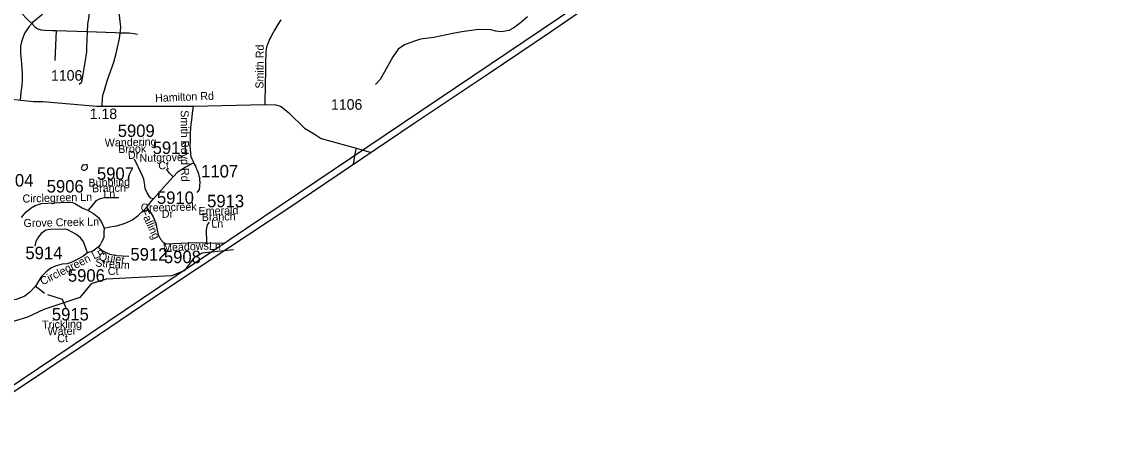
# Model space of a CAD drawing. Extents: x 1383679 to 1536984, y 460658 to 651027.
# Drawn here: x 1405913 to 1418729, y 488156 to 493101 of the extents above; entities that cross this region are included whole.
import ezdxf

# ---------------------------------------------------------------- set-up
doc = ezdxf.new("R2010")
doc.units = 0
for name, color, linetype in [('Default', 7, 'Continuous'), ('Exist Boundary Political City Limit New', 7, 'Continuous'), ('Exist Boundary Political StateLine', 7, 'Continuous'), ('Exist Hydrographic Creek Single Shore', 7, 'Continuous'), ('Exist Hydrographic Misc Water Feature', 7, 'Continuous'), ('Exist Road Non-System Secondary Historical Number Label', 7, 'Continuous'), ('Exist Road Non-System Type 51', 7, 'Continuous'), ('Exist Road Non-System Type 51 Label', 7, 'Continuous'), ('Exist Road Secondary Mileage Hundredths English Label', 7, 'Continuous'), ('Exist Road Secondary Type 51 Attributed', 7, 'Continuous'), ('Exist Road Secondary Type 51 Label', 7, 'Continuous'), ('Exist Road Secondary Type 51 Number Label', 7, 'Continuous'), ('Map Preparation Boundary City Limit Buffer Line', 7, 'Continuous')]:
    doc.layers.add(name, color=color, linetype=linetype)

msp = doc.modelspace()

# ---------------------------------------------------------------- linework, layer by layer
at = {"layer": 'Default'}
msp.add_lwpolyline([(1418935, 497828), (1418342, 497382), (1417593, 496830), (1416984, 496373), (1416229, 495820), (1415794, 495504), (1404876, 488156)], dxfattribs=at)
at = {"layer": 'Exist Boundary Political City Limit New'}
msp.add_lwpolyline([(1418935, 497828), (1418342, 497382), (1417593, 496830), (1416984, 496373), (1416229, 495820), (1415794, 495504), (1404876, 488156)], dxfattribs=at)
at = {"layer": 'Exist Boundary Political StateLine'}
msp.add_lwpolyline([(1418935, 497828), (1418342, 497382), (1417593, 496830), (1416984, 496373), (1416229, 495820), (1415409, 495224), (1414916, 494852), (1414652, 494666), (1413810, 494099), (1412999, 493532), (1412192, 492975), (1411452, 492477), (1410572, 491891), (1409804, 491375), (1409060, 490873), (1408385, 490425), (1407598, 489902), (1406702, 489298), (1405746, 488656)], dxfattribs=at)
at = {"layer": 'Exist Hydrographic Creek Single Shore'}
msp.add_lwpolyline([(1408427, 490392), (1408055, 490355), (1407962, 490301), (1407843, 490142), (1407692, 490086), (1406915, 490046), (1406739, 489991), (1406603, 489826), (1406175, 489684), (1405981, 489596), (1405604, 489479)], dxfattribs=at)
at = {"layer": 'Exist Hydrographic Misc Water Feature'}
for points in [[(1411916, 493157), (1411834, 493085), (1411757, 493026), (1411697, 492996), (1411608, 492979), (1411540, 492988), (1411483, 493002), (1411335, 493006), (1411136, 492978), (1411032, 492961), (1410805, 492911), (1410648, 492892), (1410564, 492865), (1410459, 492824), (1410384, 492775), (1410320, 492682), (1410222, 492506), (1410169, 492413), (1410115, 492356)], [(1406691, 491404), (1406655, 491399), (1406635, 491396), (1406631, 491385), (1406620, 491360), (1406626, 491346), (1406650, 491339), (1406664, 491338), (1406680, 491345), (1406690, 491358), (1406695, 491368), (1406691, 491404)]]:
    msp.add_lwpolyline(points, dxfattribs=at)
at = {"layer": 'Exist Road Non-System Type 51'}
for q in [(1406309, 492639), (1406692, 492982)]:
    msp.add_line((1406324, 492994), q, dxfattribs=at)
for points in [[(1405098, 493728), (1405117, 493706), (1405147, 493701), (1405289, 493687), (1405330, 493683), (1405359, 493675), (1405389, 493660), (1405418, 493641), (1405663, 493443), (1405870, 493251), (1405915, 493198), (1405975, 493135), (1406034, 493078)], [(1406457, 493650), (1406403, 493551), (1406330, 493410), (1406289, 493344), (1406246, 493280), (1406199, 493227), (1406146, 493174), (1406079, 493118), (1406044, 493090), (1406034, 493078)], [(1406988, 493622), (1406826, 493591), (1406800, 493581), (1406770, 493559), (1406748, 493536), (1406734, 493511), (1406724, 493482), (1406721, 493453), (1406721, 493419), (1406722, 493366), (1406722, 493330), (1406721, 493294), (1406705, 493133), (1406700, 493097), (1406697, 493067), (1406692, 492982)], [(1407083, 492966), (1407087, 492992), (1407089, 493040), (1407084, 493103), (1407074, 493178), (1407057, 493264), (1407006, 493527), (1406988, 493622)], [(1406034, 493078), (1405998, 493038), (1405961, 492980), (1405944, 492953), (1405922, 492896), (1405912, 492862), (1405901, 492809), (1405898, 492768), (1405898, 492765)], [(1406034, 493078), (1406070, 493038), (1406104, 493017), (1406146, 493003), (1406189, 492998), (1406274, 492995), (1406324, 492994)], [(1408988, 493122), (1408955, 493066), (1408915, 492998), (1408875, 492927), (1408869, 492915), (1408856, 492891), (1408846, 492869), (1408843, 492861), (1408838, 492850), (1408834, 492839), (1408830, 492828), (1408825, 492812), (1408821, 492794), (1408817, 492779), (1408815, 492763), (1408813, 492747), (1408812, 492731), (1408811, 492713), (1408811, 492697), (1408809, 492651), (1408806, 492505), (1408803, 492367), (1408800, 492119)], [(1406692, 492982), (1406685, 492795), (1406682, 492744), (1406677, 492692), (1406669, 492644), (1406627, 492401), (1406618, 492376), (1406598, 492355)], [(1406692, 492982), (1407023, 492971), (1407083, 492966)], [(1406868, 492098), (1406874, 492198), (1406881, 492239), (1406895, 492289), (1406934, 492408), (1407006, 492621), (1407036, 492722), (1407074, 492900), (1407083, 492966)], [(1407083, 492966), (1407148, 492968), (1407190, 492968), (1407248, 492961), (1407290, 492951)], [(1405898, 492765), (1405901, 492723), (1405908, 492649), (1405916, 492546), (1405921, 492478), (1405919, 492413), (1405914, 492342), (1405905, 492258), (1405896, 492173)], [(1407949, 492098), (1407939, 492016), (1407928, 491933), (1407922, 491886), (1407917, 491834), (1407914, 491786), (1407913, 491725), (1407912, 491681), (1407911, 491631), (1407912, 491584), (1407916, 491540), (1407919, 491519), (1407922, 491505), (1407926, 491493), (1407933, 491474), (1407948, 491441), (1407954, 491427)], [(1409853, 491408), (1409872, 491533), (1409880, 491568), (1409889, 491601)], [(1407479, 490997), (1407447, 491005), (1407427, 491028), (1407402, 491068), (1407381, 491122), (1407373, 491182), (1407365, 491233), (1407344, 491277), (1407251, 491469)], [(1407711, 491258), (1407771, 491324), (1407856, 491372), (1407954, 491427)], [(1407954, 491427), (1407976, 491384), (1407986, 491362), (1407995, 491339), (1408003, 491317), (1408011, 491295), (1408017, 491275), (1408018, 491271), (1408023, 491250), (1408025, 491238), (1408026, 491224), (1408028, 491195), (1408026, 491151), (1408025, 491136), (1408023, 491128), (1408022, 491121), (1408019, 491109), (1408013, 491097), (1408006, 491087), (1407998, 491078), (1407994, 491074)], [(1407479, 490997), (1407603, 491140), (1407711, 491258)], [(1407711, 491258), (1407669, 491304), (1407634, 491351)], [(1406702, 490860), (1406752, 490916), (1406800, 490977), (1406839, 490998), (1406895, 491015), (1407066, 491015)], [(1407394, 490894), (1407452, 490968), (1407479, 490997)], [(1405912, 490776), (1405965, 490840), (1406027, 490892), (1406075, 490920), (1406149, 490942), (1406371, 490955), (1406508, 490959), (1406551, 490940), (1406633, 490892), (1406702, 490860)], [(1406702, 490860), (1406765, 490825), (1406824, 490776), (1406867, 490713), (1406891, 490652)], [(1406891, 490652), (1406960, 490664), (1407045, 490678), (1407141, 490709), (1407220, 490745), (1407298, 490801), (1407394, 490894)], [(1407394, 490894), (1407439, 490845), (1407474, 490783), (1407506, 490710), (1407520, 490626), (1407534, 490574), (1407561, 490518), (1407592, 490483), (1407624, 490464), (1407990, 490481), (1408113, 490476)], [(1408113, 490476), (1408107, 490630), (1408119, 490688), (1408144, 490723)], [(1406697, 490357), (1406675, 490414), (1406647, 490488), (1406614, 490530), (1406564, 490573), (1406505, 490606), (1406461, 490632), (1406433, 490639), (1406251, 490635), (1406201, 490626), (1406144, 490587), (1406113, 490547), (1406083, 490493), (1406070, 490436)], [(1406891, 490652), (1406890, 490598), (1406888, 490534), (1406860, 490482), (1406847, 490453), (1406823, 490423)], [(1408113, 490476), (1408217, 490474), (1408333, 490477)], [(1406697, 490357), (1406640, 490313), (1406566, 490276), (1406501, 490241), (1406454, 490226), (1406396, 490224), (1406312, 490201), (1406259, 490175), (1406205, 490131), (1406146, 490072), (1406078, 489963)], [(1406823, 490423), (1406759, 490379), (1406697, 490357)], [(1406823, 490423), (1406882, 490379), (1406960, 490340), (1407041, 490327), (1407185, 490316)], [(1406078, 489963), (1406010, 489889), (1405953, 489845), (1405849, 489804), (1405826, 489799)], [(1406078, 489963), (1406142, 489913), (1406183, 489880)], [(1406222, 489863), (1406395, 489809), (1406441, 489695)]]:
    msp.add_lwpolyline(points, dxfattribs=at)
at = {"layer": 'Exist Road Secondary Type 51 Attributed'}
msp.add_lwpolyline([(1404032, 492358), (1404499, 492380), (1404680, 492369), (1405019, 492329), (1405393, 492253), (1405686, 492194), (1406053, 492154), (1406165, 492153), (1406805, 492097), (1407368, 492096), (1407949, 492098), (1408800, 492119), (1408932, 492115), (1408995, 492092), (1409085, 492019), (1409271, 491838), (1409384, 491770), (1409469, 491713), (1409889, 491601), (1410060, 491547)], dxfattribs=at)
at = {"layer": 'Map Preparation Boundary City Limit Buffer Line'}
msp.add_lwpolyline([(1418935, 497828), (1418342, 497382), (1417593, 496830), (1416984, 496373), (1416229, 495820), (1415794, 495504), (1404876, 488156)], dxfattribs=at)
msp.add_lwpolyline([(1418935, 497828), (1418342, 497382), (1417593, 496830), (1416984, 496373), (1416229, 495820), (1415794, 495504), (1404876, 488156)], dxfattribs=at)

# ---------------------------------------------------------------- texts
at = {"layer": 'Exist Road Non-System Secondary Historical Number Label'}
for s, p in [('5909', (1407054, 491732)), ('5911', (1407468, 491530)), ('5907', (1406807, 491224)), ('1107', (1408044, 491252)), ('5904', (1405614, 491144)), ('5906', (1406211, 491073)), ('5910', (1407519, 490938)), ('5913', (1408115, 490898)), ('5914', (1405958, 490282)), ('5912', (1407205, 490266)), ('5908', (1407602, 490235)), ('5906', (1406462, 490015)), ('5915', (1406272, 489555))]:
    msp.add_text(s, height=147.6, dxfattribs=at).set_placement(p)
at = {"layer": 'Exist Road Non-System Type 51 Label'}
for s, rotation, p in [('Smith Boyd Rd', 270.4274, (1407801, 492049)), ('Wandering', 1.2116, (1406901, 491617)), ('Brook', 1.2116, (1407061, 491541)), ('Dr', 1.2116, (1407176, 491471)), ('Nutgrove', 1.2116, (1407313, 491436)), ('Ct', 1.2116, (1407536, 491347)), ('Bubbling', 1.2116, (1406707, 491142)), ('Branch', 1.2116, (1406749, 491075)), ('Circlegreen Ln', 1.5495, (1405925, 490953)), ('Ln', 1.2116, (1406884, 491009)), ('Falling', 294.0833, (1407322, 490849)), ('Greencreek', 1.2116, (1407328, 490845)), ('Dr', 1.2116, (1407577, 490772)), ('Emerald', 1.2116, (1408014, 490806)), ('Grove Creek Ln', 1.1584, (1405937, 490663)), ('Branch', 1.2116, (1408051, 490735)), ('Ln', 1.2116, (1408165, 490655)), ('Meadows', 2.7287, (1407594, 490371)), ('Ln', 358.9381, (1408136, 490392)), ('Circlegreen Ln', 26.5854, (1406161, 489970)), ('Quiet', 350.9526, (1406824, 490271)), ('Stream', 355.5974, (1406785, 490195)), ('Ct', 2.9336, (1406938, 490092)), ('Trickling', 1.2116, (1406157, 489458)), ('Water', 1.2116, (1406222, 489379)), ('Ct', 1.2116, (1406337, 489296))]:
    msp.add_text(s, height=95, rotation=rotation, dxfattribs=at).set_placement(p)
at = {"layer": 'Exist Road Secondary Mileage Hundredths English Label'}
msp.add_text('1.18', height=125, rotation=359.8136, dxfattribs=at).set_placement((1406721, 491945))
at = {"layer": 'Exist Road Secondary Type 51 Label'}
for s, rotation, p in [('Smith Rd', 89.5258, (1408783, 492305)), ('Hamilton Rd', 2.2643, (1407499, 492147))]:
    msp.add_text(s, height=95, rotation=rotation, dxfattribs=at).set_placement(p)
at = {"layer": 'Exist Road Secondary Type 51 Number Label'}
for p in [(1406262, 492400), (1409585, 492055)]:
    msp.add_text('1106', height=125, dxfattribs=at).set_placement(p)

doc.saveas('drawing.dxf')
